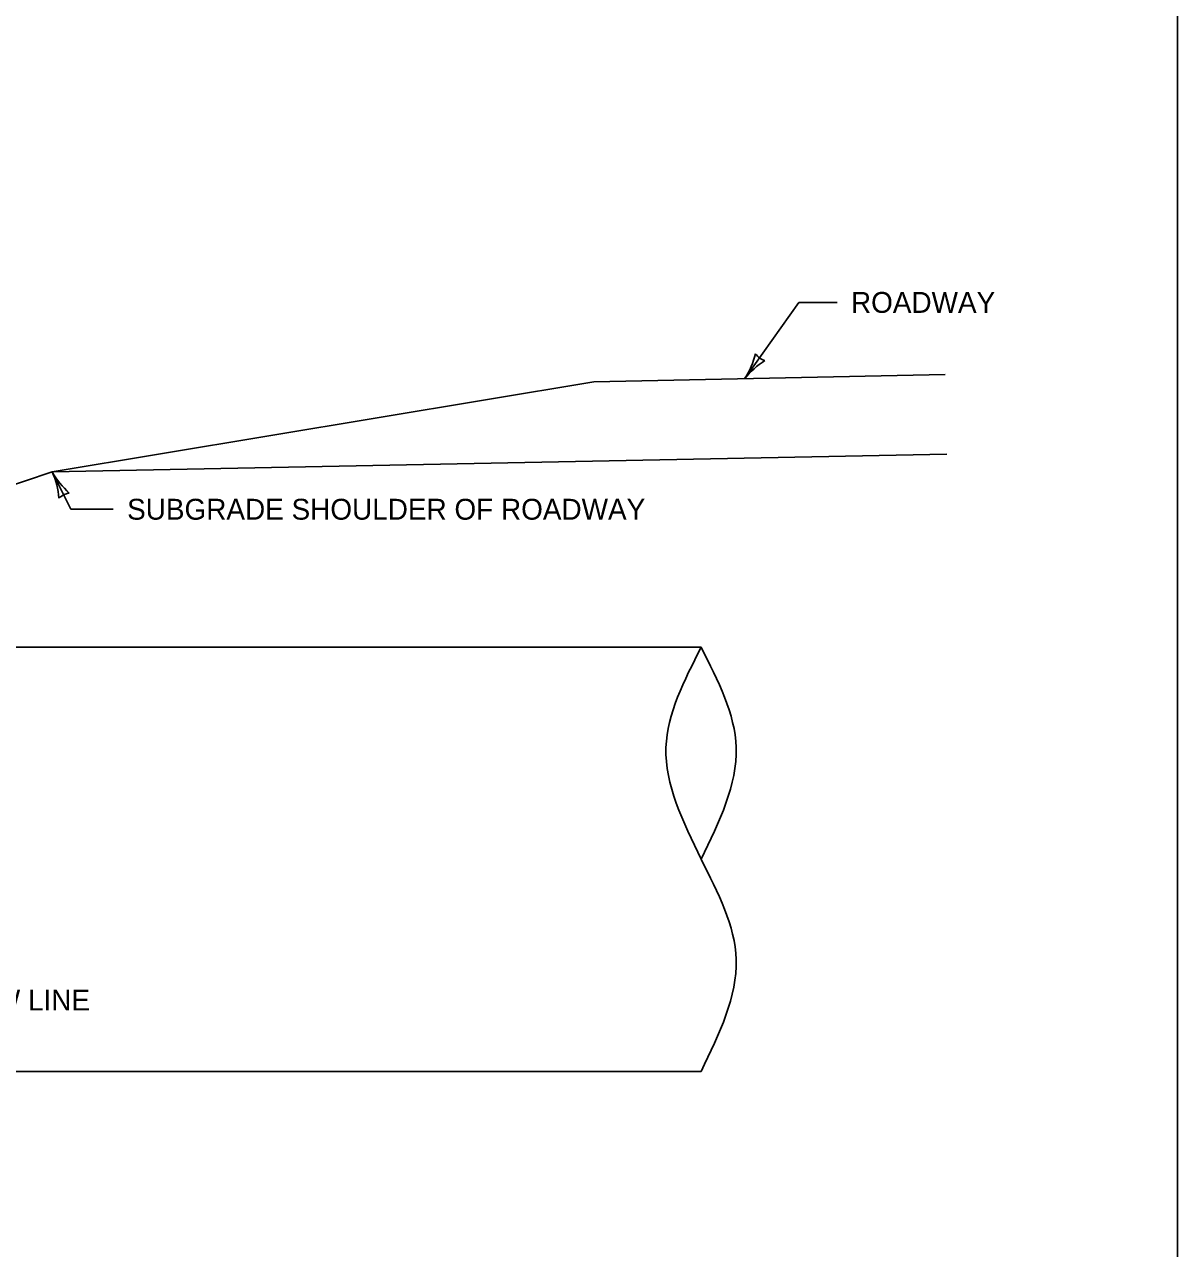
# Model space of a CAD drawing. Extents: x 49991.4 to 50021, y 49987.6 to 50011.4.
# Drawn here: x 50005.301 to 50008.615, y 50004.23 to 50007.746 of the extents above; entities that cross this region are included whole.
import ezdxf

# ---------------------------------------------------------------- set-up
doc = ezdxf.new("R2010")
doc.units = 0
for name, color, linetype in [('Level 1', 7, 'Continuous'), ('Level 2', 7, 'Continuous'), ('Level 3', 7, 'Continuous'), ('Level 4', 7, 'Continuous')]:
    doc.layers.add(name, color=color, linetype=linetype)

msp = doc.modelspace()

# ---------------------------------------------------------------- linework, layer by layer
at = {"layer": 'Level 1'}
for p, q in [((50005.3807, 50006.4608), (50007.9513, 50006.5123)), ((50004.6593, 50006.2203), (50005.3807, 50006.4608)), ((50004.7215, 50005.957), (50007.2456, 50005.957)), ((50002.3102, 50004.7389), (50007.2456, 50004.7389))]:
    msp.add_line(p, q, dxfattribs=at)
msp.add_lwpolyline([(50008.6146, 50011.2628), (50000.3356, 50011.2628), (50000.3356, 50000.0624), (50008.6146, 50000.0624)], close=True, dxfattribs=at)
for points in [[(50007.2456, 50005.957), (50007.1446, 50005.6693), (50007.2456, 50005.348)], [(50007.2456, 50005.957), (50007.3464, 50005.6693), (50007.2456, 50005.348)], [(50007.2456, 50005.348), (50007.3464, 50005.0604), (50007.2456, 50004.7389)]]:
    msp.add_spline(points, degree=3, dxfattribs=at)
at = {"layer": 'Level 3'}
for p, q in [((50007.3707, 50006.7289), (50007.5263, 50006.9479)), ((50007.5263, 50006.9479), (50007.6361, 50006.9479)), ((50005.4345, 50006.3537), (50005.3807, 50006.4608)), ((50005.4345, 50006.3537), (50005.556, 50006.3537))]:
    msp.add_line(p, q, dxfattribs=at)
for centre, radius, start, end in [((50007.1753, 50006.8559), 0.233, 326.9829, 346.2328), ((50007.4458, 50006.8328), 0.0548, 216.2944, 252.0168), ((50007.5454, 50006.5914), 0.2223, 121.6116, 141.7951), ((50005.1781, 50006.3692), 0.2223, 4.128, 24.3115), ((50005.5835, 50006.5755), 0.233, 209.4993, 228.7491), ((50005.4383, 50006.3462), 0.0548, 98.8108, 134.5331)]:
    msp.add_arc(centre, radius, start, end, dxfattribs=at)
at = {"layer": 'Level 4'}
for p, q in [((50006.9374, 50006.7202), (50007.9467, 50006.7404)), ((50005.3807, 50006.4608), (50006.9374, 50006.7202))]:
    msp.add_line(p, q, dxfattribs=at)

# ---------------------------------------------------------------- texts
at = {"layer": 'Level 2'}
for s, p in [('ROADWAY', (50007.6761, 50006.9179)), ('SUBGRADE SHOULDER OF ROADWAY', (50005.596, 50006.3237)), ('FLOW LINE', (50005.0571, 50004.9137))]:
    msp.add_text(s, height=0.06, dxfattribs=at).set_placement(p)

doc.saveas('drawing.dxf')
